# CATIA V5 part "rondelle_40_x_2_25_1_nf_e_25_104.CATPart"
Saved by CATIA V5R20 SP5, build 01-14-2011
Part number: rondelle_40_x_2_25_1_nf_e_25_104
Definition: Rondelle ressort 40 x 2.25; NF E 25-104 1ere serie
Description: Rondelle ressort 40 x 2.25; NF E 25-104 1ere serie
Property "DESIGN": "Rondelle ressort 40 x 2.25; NF E 25-104 1ere serie"
Property "DESIGN": "Rondelle ressort 40 x 2.25; NF E 25-104 1ere serie"
Property "STANDARD": "NF E25-104"
Property "STANDARD": "NF E25-104"
Property "AUTHOR": "TraceParts S.A."
Property "AUTHOR": "TraceParts S.A."
Property "WEB": "www.traceparts.com"
Property "WEB": "www.traceparts.com"
Property "TRACEPARTS": "TRACEPARTS"
Property "TraceParts.PartStatus": "Published"
Property "TraceParts.PartNumber": "10-31072008-111016"
Property "TraceParts.PartVersion": "1.0.6"
Property "TraceParts.InstanceId": "10-31072008-1110162HMN1SL8VJG7RVN422QWMV0V4"
Property "TraceParts.ClassPath": "TRACE:/ROOT/C21/C21.060/C21.060.030/C21.060.030.T05/10-31072008-111016"
Bounding box of the stored display mesh (mm): x -20 to 20, y -20 to 20, z -0.9 to 2.25
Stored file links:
  X:\Enseignants\HermantG\2A\Cours ED TP\appareil de mesure de raideur\rondelle_40_x_2_25_1_nf_e_25_104.CATPart
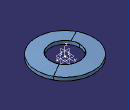
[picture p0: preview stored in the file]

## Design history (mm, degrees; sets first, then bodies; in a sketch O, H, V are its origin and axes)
AxisSystem1: origin (0, 0, 0), X (1, 0, 0), Y (0, 1, 0), Z (0, 0, 1)
Body1 "rondelle_40_x_2_25_1_nf_e_25_104" (main body)
  Solid1: solid without history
